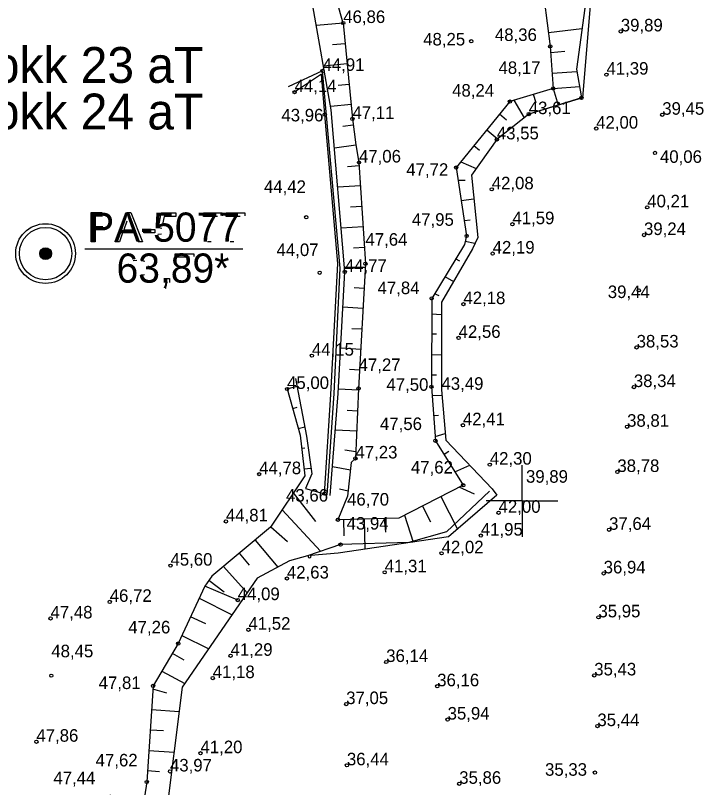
# Model space of a CAD drawing. Extents: x 700746 to 706058, y 6570320 to 6580460.
# Drawn here: x 702901 to 703035.5, y 6575844 to 6575994.8 of the extents above; entities that cross this region are included whole.
import ezdxf

# ---------------------------------------------------------------- set-up
doc = ezdxf.new("R2010")
doc.units = 0
for name, color, linetype in [('GEOLPUNKT', 7, 'Continuous'), ('KORGUS-EH2000', 7, 'Continuous'), ('Plokid', 7, 'Continuous'), ('RELJEEF', 7, 'Continuous'), ('VEEKOGU', 7, 'Continuous'), ('VORK', 7, 'Continuous')]:
    doc.layers.add(name, color=color, linetype=linetype)

msp = doc.modelspace()

# ---------------------------------------------------------------- linework, layer by layer
at = {"layer": 'GEOLPUNKT'}
msp.add_line((702914.57, 6575949.22), (702945.49, 6575949.22), dxfattribs=at)
msp.add_line((702914.57, 6575949.22), (702945.49, 6575949.22), dxfattribs=at)
for points in [[(702915.86, 6575950.62), (702915.86, 6575956.32), (702918.01, 6575956.32)], [(702920.55, 6575950.62), (702922.74, 6575956.32), (702923.56, 6575956.32), (702925.88, 6575950.62), (702925.02, 6575950.62), (702924.36, 6575952.34), (702921.97, 6575952.34), (702921.35, 6575950.62), (702920.55, 6575950.62)], [(702929.63, 6575953.23), (702928.98, 6575953.32), (702929.53, 6575956.24), (702932.36, 6575956.24), (702932.36, 6575955.57), (702930.09, 6575955.57), (702929.78, 6575954.04)], [(702937.75, 6575955.57), (702937.75, 6575956.24), (702941.44, 6575956.24), (702941.44, 6575955.7)], [(702942.18, 6575955.57), (702942.18, 6575956.24), (702945.87, 6575956.24), (702945.87, 6575955.7)], [(702918.07, 6575955.64), (702916.61, 6575955.64), (702916.61, 6575953.61)], [(702922.82, 6575954.63), (702922.19, 6575952.96)], [(702922.19, 6575952.96), (702924.13, 6575952.96), (702923.53, 6575954.54)], [(702940.54, 6575955.57), (702937.75, 6575955.57)], [(702944.97, 6575955.57), (702942.18, 6575955.57)], [(702916.61, 6575953.61), (702918.09, 6575953.61)], [(702926.12, 6575952.33), (702926.12, 6575953.03), (702928.27, 6575953.03), (702928.27, 6575952.33), (702926.12, 6575952.33)], [(702918.08, 6575952.93), (702916.61, 6575952.93), (702916.61, 6575950.62), (702915.86, 6575950.62)], [(702928.85, 6575952.11), (702929.59, 6575952.17)], [(702939.27, 6575950.62), (702938.55, 6575950.62)], [(702943.7, 6575950.62), (702942.98, 6575950.62)], [(702932.23, 6575947.57), (702932.23, 6575948.24), (702935.92, 6575948.24), (702935.92, 6575947.7)], [(702935.02, 6575947.57), (702932.23, 6575947.57)], [(702924.75, 6575946.92), (702924.06, 6575946.86)], [(702926.32, 6575946.74), (702925.62, 6575946.86)], [(702926.93, 6575945.32), (702927.01, 6575945.93)], [(702925.55, 6575944.13), (702926.25, 6575944.22)], [(702930.35, 6575942.62), (702930.35, 6575943.41), (702931.15, 6575943.41), (702931.15, 6575942.62)], [(702930.75, 6575942.62), (702930.35, 6575942.62)], [(702933.75, 6575942.62), (702933.03, 6575942.62)], [(702930.5, 6575941.49), (702930.3, 6575941.79)]]:
    msp.add_lwpolyline(points, dxfattribs=at)
for radius in [5.84, 5.12, 1.15, 1.02, 0.896, 0.768, 0.64, 0.512, 0.384, 0.256, 0.128]:
    msp.add_circle((702906.93, 6575948.3), radius, dxfattribs=at)
at = {"layer": 'KORGUS-EH2000'}
for centre in [(702965.07, 6575993.34), (703019.29, 6575991.7), (702990.07, 6575989.77), (703005.51, 6575988.76), (702961.03, 6575983.99), (703016.49, 6575983.25), (703006.08, 6575980.55), (702955.57, 6575979.83), (703011.59, 6575978.72), (702997.62, 6575978), (702961.46, 6575975.45), (703001.31, 6575975.54), (703027.39, 6575975.42), (702966.86, 6575974.61), (703014.48, 6575972.71), (702995.08, 6575970.61), (703025.97, 6575967.96), (702968.15, 6575966.09), (702987.13, 6575965.11), (702994.08, 6575960.85), (703024.46, 6575957.33), (702957.84, 6575955.4), (702998.12, 6575954.04), (702989.18, 6575951.75), (703023.82, 6575951.92), (702994.26, 6575948.31), (702969.41, 6575946.31), (702960.47, 6575944.56), (702965.37, 6575944.71), (703022.79, 6575941.12), (702982.35, 6575939.54), (702988.54, 6575938.42), (702987.61, 6575931.84), (703022.38, 6575929.96), (702958.96, 6575928.36), (702954.1, 6575921.85), (702968.08, 6575921.95), (702982.29, 6575922.27), (703021.84, 6575922.23), (702988.45, 6575914.77), (703020.52, 6575914.48), (702983.08, 6575911.74), (702967.46, 6575908.28), (702993.7, 6575907.07), (702948.65, 6575905.21), (703018.62, 6575905.64), (702988.52, 6575903.06), (702961.42, 6575901.4), (702995.42, 6575897.67), (702942.16, 6575895.99), (702964.03, 6575896.3), (703017, 6575894.34), (702991.95, 6575893.22), (702964.54, 6575891.45), (702984.29, 6575889.75), (702931.33, 6575887.34), (702954.07, 6575884.83), (702973.17, 6575886.04), (703015.94, 6575885.83), (702944.47, 6575880.61), (702919.46, 6575880.27), (702907.9, 6575877.03), (703014.92, 6575877.24), (702946.56, 6575874.83), (702932.84, 6575872.12), (702943.07, 6575869.73), (702973.47, 6575868.52), (702908.05, 6575865.85), (702939.58, 6575865.37), (703014.1, 6575865.9), (702927.93, 6575863.84), (702983.43, 6575863.78), (702965.65, 6575860.3), (702985.46, 6575857.28), (703014.72, 6575856), (702905.13, 6575852.95), (702937.19, 6575850.71), (702931.23, 6575847.14), (702965.79, 6575848.34), (703014.23, 6575846.92), (702926.69, 6575845.08), (702987.73, 6575844.73)]:
    msp.add_circle(centre, 0.32, dxfattribs=at)
at = {"layer": 'RELJEEF'}
for p, q in [((702965.07, 6575993.34), (702959.84, 6575992.84)), ((703005.15, 6575991.48), (703011.71, 6575992.28)), ((702962.99, 6575989.13), (702965.45, 6575989.36)), ((703008.36, 6575987.75), (703005.6, 6575987.5)), ((702965.83, 6575985.38), (702961.23, 6575984.94)), ((703005.87, 6575983.51), (703010.7, 6575983.85)), ((702964.07, 6575981.19), (702966.21, 6575981.4)), ((703006.08, 6575980.55), (703011.21, 6575980.91)), ((703006.08, 6575980.55), (703007.07, 6575977.26)), ((703002.75, 6575977.75), (703002.25, 6575979.4)), ((702966.59, 6575977.42), (702962.63, 6575977.02)), ((702998.42, 6575978.24), (703000.43, 6575974.81)), ((702996.95, 6575974.33), (702995.62, 6575975.54)), ((702965.02, 6575973.2), (702967.02, 6575973.44)), ((702993.1, 6575972.44), (702995.22, 6575970.72)), ((702967.55, 6575969.48), (702963.37, 6575968.86)), ((702991.72, 6575968.41), (702990.57, 6575969.34)), ((702965.93, 6575965.28), (702968.18, 6575965.53)), ((702988.05, 6575966.24), (702991.05, 6575964.91)), ((702988.88, 6575962.6), (702987.52, 6575962.59)), ((702968.44, 6575961.54), (702964, 6575961.25)), ((702966.51, 6575957.41), (702968.69, 6575957.54)), ((702988.12, 6575958.64), (702990.6, 6575959.02)), ((702989.87, 6575954.8), (702988.73, 6575954.69)), ((702968.95, 6575953.55), (702964.66, 6575953.28)), ((702988.91, 6575950.75), (702990.81, 6575950.32)), ((702967.1, 6575949.45), (702969.2, 6575949.56)), ((702987.82, 6575946.8), (702987.03, 6575947.25)), ((702969.37, 6575945.57), (702965.3, 6575945.6)), ((702984.95, 6575943.83), (702986.59, 6575942.84)), ((702967.18, 6575941.68), (702969.15, 6575941.57)), ((702983.84, 6575940.07), (702982.88, 6575940.41)), ((702968.93, 6575937.58), (702965.01, 6575937.8)), ((702982.34, 6575936.56), (702984.26, 6575936.42)), ((702966.75, 6575933.69), (702968.71, 6575933.59)), ((702983.29, 6575932.56), (702982.33, 6575932.56)), ((702968.49, 6575929.59), (702964.58, 6575929.81)), ((702982.31, 6575928.56), (702984.26, 6575928.55)), ((702966.32, 6575925.71), (702968.28, 6575925.6)), ((702983.28, 6575924.57), (702982.3, 6575924.56)), ((702954.1, 6575921.85), (702956.06, 6575922.4)), ((702968.06, 6575921.6), (702964.16, 6575921.8)), ((702982.42, 6575920.56), (702984.35, 6575920.67)), ((702956, 6575918.23), (702955.19, 6575918)), ((702965.87, 6575917.7), (702967.88, 6575917.61)), ((702983.71, 6575916.65), (702982.72, 6575916.58)), ((702956.28, 6575914.15), (702957.58, 6575914.44)), ((702967.7, 6575913.61), (702963.54, 6575913.8)), ((702983.02, 6575912.59), (702985.01, 6575913.13)), ((702957.59, 6575910.31), (702956.95, 6575910.22)), ((702965.38, 6575909.96), (702967.52, 6575909.62)), ((702985.73, 6575909.62), (702984.76, 6575909.07)), ((702957.39, 6575906.24), (702958.78, 6575906.4)), ((702966.49, 6575905.96), (702962.96, 6575906.65)), ((702986.88, 6575905.68), (702989.77, 6575906.94)), ((702964.34, 6575902.35), (702966.05, 6575901.98)), ((702990.73, 6575901.31), (702987.7, 6575902.65)), ((702959.7, 6575895.99), (702955.34, 6575901.56)), ((702984.14, 6575900.82), (702987.4, 6575894.48)), ((702982.2, 6575895.85), (702980.58, 6575899)), ((702953.13, 6575898.22), (702960.61, 6575890.2)), ((702965.25, 6575893.15), (702965.16, 6575896.33)), ((702969.16, 6575896.43), (702969.31, 6575890.56)), ((702973.42, 6575893.87), (702973.16, 6575896.54)), ((702977.02, 6575897.18), (702978.75, 6575891.96)), ((702954.18, 6575891.98), (702950.92, 6575894.89)), ((702947.86, 6575892.31), (702952.29, 6575887.03)), ((702946.73, 6575887.42), (702944.79, 6575889.76)), ((702941.71, 6575887.2), (702946.32, 6575882.02)), ((702941.83, 6575882.17), (702938.83, 6575884.46)), ((702936.94, 6575880.96), (702943.37, 6575877.73)), ((702938.22, 6575875.95), (702935.26, 6575877.33)), ((702933.57, 6575873.7), (702938.79, 6575871.09)), ((702934.02, 6575868.86), (702931.69, 6575870.18)), ((702929.65, 6575866.73), (702934.12, 6575864.3)), ((702930.64, 6575862.46), (702927.89, 6575863.21)), ((702927.63, 6575859.21), (702933.02, 6575858.86)), ((702929.94, 6575855.05), (702927.36, 6575855.22)), ((702927.1, 6575851.23), (702932.02, 6575850.91)), ((702929.17, 6575847.04), (702926.83, 6575847.24))]:
    msp.add_line(p, q, dxfattribs=at)
for points in [[(702952.37, 6576051.41), (702956.48, 6576044.05), (702963.52, 6576035.36), (702970.78, 6576014.57), (702978.18, 6576008), (702999.29, 6576005.18), (703006.78, 6576003.08), (703012.26, 6575996.27), (703010.62, 6575984.33), (703011.59, 6575978.72), (703001.31, 6575975.54)], [(702962.51, 6575901.07), (702964.11, 6575920.96), (702965.37, 6575944.71), (702962.74, 6575976.37), (702959.16, 6575996.69), (702953.85, 6576021.32), (702949.53, 6576045.58), (702948.27, 6576050.9)], [(702965.07, 6575993.34), (702962.7, 6576001.65), (702970.63, 6576010.11), (702978.76, 6576002.33), (702979.51, 6576001.79), (702987.25, 6576000.35), (703004.31, 6575997.91), (703005.51, 6575988.76), (703006.08, 6575980.55)], [(702965.07, 6575993.34), (702966.86, 6575974.61), (702967.54, 6575969.54), (702968.15, 6575966.09), (702969.41, 6575946.31), (702968.08, 6575921.95), (702967.46, 6575908.28), (702966.65, 6575907.48), (702965.93, 6575900.91), (702964.03, 6575896.3)], [(702961.92, 6575901.13), (702963.31, 6575921), (702964.45, 6575945.44), (702961.03, 6575983.99), (702954.33, 6575980.88)], [(702955.77, 6575923.91), (702957.92, 6575912.64), (702958.94, 6575905.29), (702957.73, 6575902.44), (702961.42, 6575901.4), (702962.63, 6575920.79), (702964, 6575946.35), (702961.46, 6575975.45), (702960.85, 6575983.36), (702955.57, 6575979.83)], [(703006.08, 6575980.55), (702997.62, 6575978), (702987.13, 6575965.11), (702989.18, 6575951.75), (702988.73, 6575950.07), (702982.35, 6575939.54), (702982.29, 6575922.27), (702983.08, 6575911.74), (702988.52, 6575903.06), (702975.91, 6575896.61), (702964.03, 6575896.3)], [(702954.1, 6575921.85), (702956.65, 6575912.85), (702957.55, 6575904.89)], [(702957.55, 6575904.89), (702950.88, 6575894.83), (702939.4, 6575885.27), (702938.05, 6575883.35), (702932.84, 6575872.12), (702927.93, 6575863.84), (702926.69, 6575845.08), (702925.26, 6575835.96), (702919.45, 6575842.55)], [(702993.63, 6575901.89), (702985.22, 6575893.92), (702977.91, 6575891.87), (702964.54, 6575891.45), (702958.06, 6575889.26)], [(702944.47, 6575880.61), (702938.05, 6575883.35)]]:
    msp.add_lwpolyline(points, dxfattribs=at)
at = {"layer": 'VEEKOGU'}
for points in [[(703013.33, 6575996.74), (703011.8, 6575978.7), (703001.33, 6575975.52), (702995.08, 6575970.61), (702990.15, 6575963.63), (702991.35, 6575951.46), (702990.29, 6575949.23), (702984.26, 6575938.8), (702984.26, 6575921.69), (702985.12, 6575911.83), (702994.14, 6575902.34), (702995.1, 6575901.12), (702985.66, 6575892.98), (702964.05, 6575889.79), (702958.74, 6575889.32)], [(703013.33, 6575996.74), (703011.8, 6575978.7), (703001.33, 6575975.52), (702995.08, 6575970.61), (702990.15, 6575963.63), (702991.35, 6575951.46), (702990.29, 6575949.23), (702984.26, 6575938.8), (702984.26, 6575921.69), (702985.12, 6575911.83), (702994.14, 6575902.34), (702995.1, 6575901.12), (702985.66, 6575892.98), (702964.05, 6575889.79), (702958.74, 6575889.32)], [(702958.22, 6575889.27), (702958.06, 6575889.26), (702954.6, 6575888.27), (702948.29, 6575884.89), (702933.62, 6575863.59), (702930.28, 6575837.16), (702934.02, 6575828.45), (702932.49, 6575821.04), (702937.33, 6575809.27), (702934.6, 6575804.41), (702920.2, 6575795.02), (702917.02, 6575790.18), (702912.52, 6575779.38), (702904.86, 6575766.7), (702900.62, 6575757), (702900.7, 6575745.44), (702893.68, 6575732.96), (702888.62, 6575708.7), (702877.91, 6575689.2)], [(702958.22, 6575889.27), (702958.06, 6575889.26), (702954.6, 6575888.27), (702948.29, 6575884.89), (702933.62, 6575863.59), (702930.28, 6575837.16), (702934.02, 6575828.45), (702932.49, 6575821.04), (702937.33, 6575809.27), (702934.6, 6575804.41), (702920.2, 6575795.02), (702917.02, 6575790.18), (702912.52, 6575779.38), (702904.86, 6575766.7), (702900.62, 6575757), (702900.7, 6575745.44), (702893.68, 6575732.96), (702888.62, 6575708.7), (702877.91, 6575689.2)]]:
    msp.add_lwpolyline(points, dxfattribs=at)
msp.add_arc((702958.49, 6575889.15), 0.3, 155.8142, 34.2576, dxfattribs=at)
msp.add_arc((702958.49, 6575889.15), 0.3, 155.8142, 34.2576, dxfattribs=at)
msp.add_arc((702958.49, 6575889.15), 0.3, 155.8142, 34.2576, dxfattribs=at)
at = {"layer": 'VORK'}
for q in [(703000, 6575907), (703000, 6575907), (702993, 6575900), (702993, 6575900), (703007, 6575900), (703000, 6575893), (703007, 6575900), (703000, 6575893)]:
    msp.add_line((703000, 6575900), q, dxfattribs=at)

# ---------------------------------------------------------------- texts
at = {"layer": 'GEOLPUNKT'}
for s, p in [('PA-5077', (702915.24, 6575950.62)), ('63,89*', (702920.79, 6575942.62))]:
    msp.add_text(s, height=5.7, dxfattribs=at).set_placement(p)
at = {"layer": 'KORGUS-EH2000'}
for s, p in [('46,86 ', (702965.07, 6575993.34)), ('39,89 ', (703019.29, 6575991.7)), ('48,36 ', (702994.7, 6575989.83)), ('48,25 ', (702980.69, 6575988.95)), ('44,91 ', (702961.03, 6575983.99)), ('48,17 ', (702995.4, 6575983.39)), ('41,39 ', (703016.49, 6575983.25)), ('44,14 ', (702955.57, 6575979.83)), ('48,24 ', (702986.34, 6575978.96)), ('43,61 ', (703001.31, 6575975.54)), ('39,45 ', (703027.39, 6575975.42)), ('43,96 ', (702953, 6575974.12)), ('47,11 ', (702966.86, 6575974.61)), ('42,00 ', (703014.48, 6575972.71)), ('43,55 ', (702995.08, 6575970.61)), ('47,06 ', (702968.15, 6575966.09)), ('40,06 ', (703026.94, 6575966.02)), ('47,72 ', (702977.39, 6575963.49)), ('44,42 ', (702949.59, 6575960.15)), ('42,08 ', (702994.08, 6575960.85)), ('40,21 ', (703024.46, 6575957.33)), ('47,95 ', (702978.48, 6575953.73)), ('41,59 ', (702998.12, 6575954.04)), ('39,24 ', (703023.82, 6575951.92)), ('47,64 ', (702969.41, 6575949.84)), ('44,07 ', (702952.05, 6575947.82)), ('42,19 ', (702994.26, 6575948.31)), ('44,77 ', (702965.37, 6575944.71)), ('47,84 ', (702971.78, 6575940.38)), ('39,44 ', (703016.75, 6575939.61)), ('42,18 ', (702988.54, 6575938.42)), ('42,56 ', (702987.61, 6575931.84)), ('38,53 ', (703022.38, 6575929.96)), ('44,15 ', (702958.96, 6575928.36)), ('47,27 ', (702968.08, 6575925.36)), ('38,34 ', (703021.84, 6575922.23)), ('45,00 ', (702954.1, 6575921.85)), ('47,50 ', (702973.51, 6575921.5)), ('43,49 ', (702984.26, 6575921.69)), ('42,41 ', (702988.45, 6575914.77)), ('38,81 ', (703020.52, 6575914.48)), ('47,56 ', (702972.25, 6575913.83)), ('47,23 ', (702967.46, 6575908.28)), ('42,30 ', (702993.7, 6575907.07)), ('47,62 ', (702978.3, 6575905.34)), ('38,78 ', (703018.62, 6575905.64)), ('44,78 ', (702948.65, 6575905.21)), ('39,89 ', (703000.77, 6575903.54)), ('43,66 ', (702953.9, 6575899.85)), ('46,70 ', (702965.82, 6575899.08)), ('42,00 ', (702995.42, 6575897.67)), ('44,81 ', (702942.16, 6575895.99)), ('43,94 ', (702965.74, 6575894.38)), ('41,95 ', (702991.95, 6575893.22)), ('37,64 ', (703017, 6575894.34)), ('42,02 ', (702984.29, 6575889.75)), ('45,60 ', (702931.33, 6575887.34)), ('41,31 ', (702973.17, 6575886.04)), ('36,94 ', (703015.94, 6575885.83)), ('42,63 ', (702954.07, 6575884.83)), ('46,72 ', (702919.46, 6575880.27)), ('44,09 ', (702944.47, 6575880.61)), ('47,48 ', (702907.9, 6575877.03)), ('35,95 ', (703014.92, 6575877.24)), ('47,26 ', (702923.09, 6575874.11)), ('41,52 ', (702946.56, 6575874.83)), ('48,45 ', (702908.05, 6575869.44)), ('41,29 ', (702943.07, 6575869.73)), ('36,14 ', (702973.47, 6575868.52)), ('41,18 ', (702939.58, 6575865.37)), ('35,43 ', (703014.1, 6575865.9)), ('47,81 ', (702917.3, 6575863.24)), ('36,16 ', (702983.43, 6575863.78)), ('37,05 ', (702965.65, 6575860.3)), ('35,94 ', (702985.46, 6575857.28)), ('35,44 ', (703014.72, 6575856)), ('47,86 ', (702905.13, 6575852.95)), ('41,20 ', (702937.19, 6575850.71)), ('47,62 ', (702916.71, 6575848.13)), ('36,44 ', (702965.79, 6575848.34)), ('43,97 ', (702931.23, 6575847.14)), ('35,33 ', (703004.49, 6575846.3)), ('47,44 ', (702908.45, 6575844.65)), ('35,86 ', (702987.73, 6575844.73))]:
    msp.add_text(s, height=2.45, dxfattribs=at).set_placement(p)
at = {"layer": 'Plokid'}
for s, p in [('Plokk 23 aT', (702888.31, 6575981.65)), ('Plokk 24 aT', (702888.31, 6575972.55))]:
    msp.add_text(s, height=7, dxfattribs=at).set_placement(p)

doc.saveas('drawing.dxf')
